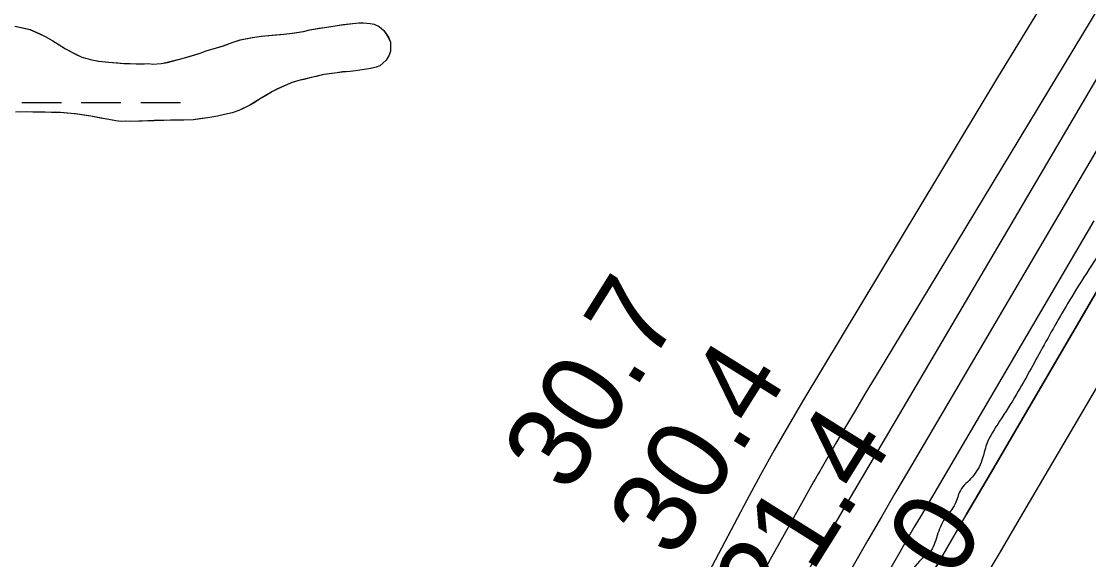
# Model space of a CAD drawing. Extents: x 3297735 to 3335592, y 670436 to 695807.
# Drawn here: x 3318492 to 3319354, y 693409 to 693844 of the extents above; entities that cross this region are included whole.
import ezdxf

# ---------------------------------------------------------------- set-up
doc = ezdxf.new("R2010")
doc.units = 0
for name, color, linetype in [('V-RIVR-EDGE', 7, 'Continuous'), ('V-RIVR-RANG', 7, 'Continuous'), ('V-SITE-VEGE', 7, 'Continuous'), ('V-TOPO-DPTH', 7, 'Continuous'), ('V-TOPO-MAJR', 7, 'Continuous'), ('V-TOPO-MINR', 7, 'Continuous'), ('V-TOPO-WATR', 7, 'Continuous'), ('V-WETL-SWMP', 7, 'Continuous')]:
    doc.layers.add(name, color=color, linetype=linetype)

msp = doc.modelspace()

# ---------------------------------------------------------------- linework, layer by layer
at = {"layer": 'V-RIVR-EDGE'}
msp.add_spline([(3319555.14, 694014.55), (3319548.52, 694002.76), (3319539.36, 693985.79), (3319509.78, 693923.27), (3319496.46, 693903), (3319479.41, 693878.17), (3319464.01, 693854.58), (3319445.27, 693818.98), (3319424.44, 693775.51), (3319406.53, 693740.74), (3319395.69, 693713), (3319386.52, 693693.13), (3319372.79, 693671.61), (3319340.34, 693621.53), (3319316.61, 693580.14), (3319295.79, 693542.89), (3319282.06, 693520.96), (3319271.65, 693502.33), (3319267.89, 693489.49), (3319259.98, 693475.83), (3319250.42, 693465.08), (3319246.25, 693454.32), (3319237.93, 693442.32), (3319231.68, 693428.65), (3319225.43, 693414.99), (3319219.61, 693410.03), (3319205.47, 693391.42), (3319185.09, 693363.28), (3319164.7, 693327.69), (3319143.08, 693301.21), (3319109.39, 693253.21), (3319083.6, 693218.46), (3319061.14, 693187.85), (3319039.52, 693157.64), (3319018.29, 693123.29), (3318994.59, 693091.02), (3318949.68, 693031.86), (3318931.37, 693004.55), (3318913.08, 692981.38), (3318902.25, 692962.76), (3318892.68, 692944.55), (3318876.03, 692916.4), (3318861.86, 692887.84), (3318841.46, 692848.51), (3318822.29, 692807.53), (3318806.46, 692774.41), (3318803.1, 692758.66), (3318804.31, 692744.98), (3318808.02, 692734.61), (3318808.84, 692730.46), (3318817.11, 692725.47), (3318826.63, 692719.23), (3318832.83, 692713), (3318835.72, 692705.53), (3318835.27, 692692.27), (3318829.85, 692681.5), (3318819.88, 692669.09), (3318809.47, 692651.3), (3318783.24, 692602.87), (3318768.67, 692580.52), (3318760.79, 692575.98), (3318753.73, 692573.1), (3318747.11, 692573.94), (3318739.24, 692579.76), (3318735.53, 692585.58), (3318730.56, 692588.49), (3318721.44, 692588.1), (3318700.27, 692573.64), (3318679.48, 692549.66), (3318660.76, 692522.35), (3318646.6, 692493.37), (3318637.03, 692477.64), (3318624.96, 692456.95), (3318607.08, 692434.19), (3318599.98, 692413.49), (3318583.3, 692372.49), (3318565.82, 692342.28), (3318547.09, 692313.73), (3318534.2, 692295.52), (3318512.56, 692258.69), (3318488.02, 692224.76), (3318446.4, 692155.23), (3318418.11, 692112.61), (3318397.31, 692084.47), (3318386.91, 692066.68), (3318376.5, 692048.05), (3318354.44, 692011.22), (3318333.22, 691976.45), (3318316.13, 691940.02), (3318301.57, 691917.67), (3318275.38, 691884.99), (3318265.81, 691873), (3318250.82, 691844.85), (3318236.64, 691808.41), (3318222.07, 691781.09), (3318194.96, 691714.01), (3318179.96, 691684.2), (3318162.07, 691654.82), (3318140.84, 691619.64), (3318130.44, 691603.92), (3318120.89, 691595.24), (3318105.09, 691577.87), (3318090.12, 691558.42), (3318067.68, 691532.37), (3318043.56, 691501.75), (3318020.26, 691465.75), (3317998.21, 691433.06), (3317973.66, 691392.92), (3317962.42, 691371.81), (3317929.95, 691315.1), (3317907.9, 691282.41), (3317889.2, 691263.39), (3317870.48, 691238.16), (3317844.7, 691202.99), (3317833.05, 691186.02), (3317808.09, 691148.78), (3317780.64, 691109.47), (3317756.1, 691076.38), (3317731.98, 691045.35), (3317684.57, 690978.73), (3317668.76, 690954.73), (3317646.3, 690922.04), (3317635.48, 690907.15), (3317629.25, 690900.53), (3317620.1, 690889.36), (3317608.46, 690874.47), (3317601.4, 690867.03), (3317592.67, 690860.42), (3317585.59, 690845.93), (3317576.86, 690836), (3317565.64, 690821.11), (3317549.42, 690801.25), (3317522.4, 690767.75), (3317502.45, 690745), (3317489.97, 690727.62), (3317482.47, 690713.55), (3317479.54, 690701.12), (3317475.78, 690689.94), (3317474.94, 690683.31), (3317467.87, 690674.21), (3317451.65, 690653.94), (3317427.54, 690622.91), (3317406.33, 690593.95), (3317381.8, 690564.58), (3317328.18, 690504.62), (3317308.23, 690483.11), (3317290.78, 690466.16), (3317272.5, 690446.31), (3317248.81, 690422.74), (3317230.94, 690402.48), (3317202.23, 690356.54), (3317170.21, 690314.34), (3317129.47, 690266.36), (3317099.12, 690227.48), (3317085.82, 690212.59), (3317074.19, 690204.33), (3317063.38, 690189.85), (3317045.08, 690163.78), (3317020.95, 690128.61), (3316996.82, 690093.85), (3316970.63, 690059.1), (3316926.98, 690008.23), (3316891.65, 689970.6), (3316861.71, 689930.05), (3316828.03, 689887.86), (3316809.31, 689860.13), (3316797.25, 689841.93), (3316783.53, 689825.38), (3316737.37, 689762.08), (3316714.9, 689728.98), (3316681.64, 689687.61), (3316661.69, 689665.69), (3316647.97, 689646.66), (3316619.68, 689606.11), (3316602.63, 689581.28), (3316583.49, 689551.9), (3316563.93, 689519.62), (3316547.71, 689499.35), (3316541.89, 689491.9), (3316538.57, 689488.6), (3316532.31, 689474.1), (3316523.16, 689461.28), (3316509.03, 689445.15), (3316500.29, 689431.49), (3316493.22, 689419.9), (3316485.73, 689407.9), (3316486.11, 689397.12), (3316486.48, 689375.57), (3316487.29, 689371.01), (3316491.44, 689370.17), (3316493.5, 689366.43), (3316494.29, 689352.75), (3316496.75, 689341.56), (3316502.54, 689336.57), (3316504.2, 689334.08), (3316504.18, 689328.69), (3316501.27, 689325.8), (3316488.83, 689321.27), (3316487.17, 689319.61), (3316487.16, 689316.71), (3316492.96, 689316.7), (3316502.08, 689318.33), (3316508.3, 689318.32), (3316513.27, 689314.99), (3316516.58, 689314.98), (3316524.87, 689314.55), (3316535.62, 689303.33), (3316544.71, 689293.36), (3316545.54, 689290.04), (3316543.46, 689287.97), (3316525.66, 689296.72), (3316509.92, 689304.22), (3316502.06, 689307.14), (3316490.45, 689308.41), (3316482.58, 689308.02), (3316478.02, 689308.03), (3316473.47, 689311.77), (3316449.46, 689323.85), (3316424.59, 689324.74), (3316401.79, 689323.14), (3316381.47, 689318.22), (3316366.54, 689316.18), (3316352.85, 689311.24), (3316334.16, 689295.54), (3316302.2, 689277.79), (3316275.21, 689257.14), (3316266.49, 689249.28), (3316249.02, 689224.04), (3316230.28, 689191.76), (3316217.78, 689162.78), (3316200.69, 689125.93), (3316182.37, 689092.82), (3316162.8, 689054.73), (3316141.17, 689024.94), (3316114.57, 688996.41), (3316081.77, 688971.62), (3316036.89, 688926.14), (3316007.39, 688897.61), (3315987.04, 688880.67), (3315970.01, 688865.79), (3315959.63, 688858.77), (3315957.13, 688852.14), (3315955.46, 688848.42), (3315953.91, 688835.53)], degree=3, dxfattribs=at)
at = {"layer": 'V-SITE-VEGE'}
for p, q in [((3318486.92, 693840.15), (3318493.19, 693838.94)), ((3318493.19, 693838.94), (3318499.13, 693837.4)), ((3318725.11, 693837.13), (3318736.86, 693839.26)), ((3318736.86, 693839.26), (3318742.24, 693839.89)), ((3318742.24, 693839.89), (3318748.96, 693841.06)), ((3318748.96, 693841.06), (3318759.73, 693842.33)), ((3318759.73, 693842.33), (3318764.6, 693842.78)), ((3318764.6, 693842.78), (3318768.31, 693842.86)), ((3318768.31, 693842.86), (3318773.89, 693842.49)), ((3318773.89, 693842.49), (3318777.11, 693841.72)), ((3318777.11, 693841.72), (3318781.03, 693839.96)), ((3318781.03, 693839.96), (3318784.82, 693836.68)), ((3318499.13, 693837.4), (3318506.97, 693834.04)), ((3318506.97, 693834.04), (3318511.4, 693831.95)), ((3318511.4, 693831.95), (3318517.56, 693828.38)), ((3318668.97, 693829.07), (3318678.71, 693831.15)), ((3318678.71, 693831.15), (3318685.93, 693832.16)), ((3318685.93, 693832.16), (3318704.28, 693833.77)), ((3318704.28, 693833.77), (3318711, 693834.61)), ((3318711, 693834.61), (3318719.91, 693836)), ((3318719.91, 693836), (3318725.11, 693837.13)), ((3318784.82, 693836.68), (3318788.49, 693831.2)), ((3318788.49, 693831.2), (3318790.27, 693827.19)), ((3318517.56, 693828.38), (3318527.83, 693821.88)), ((3318527.83, 693821.88), (3318536.02, 693817.52)), ((3318641.36, 693820.16), (3318655.26, 693824.36)), ((3318655.26, 693824.36), (3318663.11, 693827.24)), ((3318663.11, 693827.24), (3318668.97, 693829.07)), ((3318790.27, 693827.19), (3318790.27, 693819.94)), ((3318536.02, 693817.52), (3318540.97, 693815.28)), ((3318540.97, 693815.28), (3318549.12, 693812.94)), ((3318549.12, 693812.94), (3318554.54, 693811.88)), ((3318610.04, 693810.99), (3318623.95, 693814.52)), ((3318623.95, 693814.52), (3318636.51, 693818.36)), ((3318636.51, 693818.36), (3318641.36, 693820.16)), ((3318786.73, 693812.61), (3318781.61, 693808.1)), ((3318789.16, 693816.88), (3318786.73, 693812.61)), ((3318790.27, 693819.94), (3318789.16, 693816.88)), ((3318554.54, 693811.88), (3318562.65, 693811.06)), ((3318562.65, 693811.06), (3318574.98, 693810.17)), ((3318574.98, 693810.17), (3318584.94, 693809.73)), ((3318584.94, 693809.73), (3318591.68, 693809.89)), ((3318591.68, 693809.89), (3318594.88, 693810.13)), ((3318594.88, 693810.13), (3318598.27, 693809.53)), ((3318598.27, 693809.53), (3318605, 693810.03)), ((3318605, 693810.03), (3318610.04, 693810.99)), ((3318757.76, 693803.66), (3318751.54, 693803.18)), ((3318761.97, 693804.1), (3318757.76, 693803.66)), ((3318774.24, 693805.9), (3318761.97, 693804.1)), ((3318778.77, 693807.02), (3318774.24, 693805.9)), ((3318781.61, 693808.1), (3318778.77, 693807.02)), ((3318716.28, 693796.28), (3318710.76, 693794.64)), ((3318736.58, 693801.14), (3318716.28, 693796.28)), ((3318751.54, 693803.18), (3318736.58, 693801.14)), ((3318694.91, 693787.35), (3318685.76, 693781.91)), ((3318698.58, 693789.29), (3318694.91, 693787.35)), ((3318707.08, 693793.2), (3318698.58, 693789.29)), ((3318710.76, 693794.64), (3318707.08, 693793.2)), ((3318680.11, 693778.4), (3318676.61, 693776.46)), ((3318685.76, 693781.91), (3318680.11, 693778.4)), ((3318496.31, 693770.89), (3318487.38, 693770.68)), ((3318501.54, 693770.67), (3318496.31, 693770.89)), ((3318505.42, 693770.76), (3318501.54, 693770.67)), ((3318511.32, 693770.73), (3318505.42, 693770.76)), ((3318516.55, 693770.52), (3318511.32, 693770.73)), ((3318519.59, 693770.59), (3318516.55, 693770.52)), ((3318523.64, 693770.35), (3318519.59, 693770.59)), ((3318532.42, 693769.71), (3318523.64, 693770.35)), ((3318539.52, 693768.86), (3318532.42, 693769.71)), ((3318662.43, 693770.23), (3318656.22, 693768.74)), ((3318667.78, 693772.04), (3318662.43, 693770.23)), ((3318676.61, 693776.46), (3318667.78, 693772.04)), ((3318548.33, 693767.38), (3318539.52, 693768.86)), ((3318568.48, 693763.64), (3318548.33, 693767.38)), ((3318572.71, 693763.23), (3318568.48, 693763.64)), ((3318576.59, 693763.33), (3318572.71, 693763.23)), ((3318580.3, 693763.24), (3318576.59, 693763.33)), ((3318599.34, 693763.86), (3318580.3, 693763.24)), ((3318607.27, 693763.88), (3318599.34, 693763.86)), ((3318612.65, 693764.17), (3318607.27, 693763.88)), ((3318623.44, 693764.26), (3318612.65, 693764.17)), ((3318631.19, 693764.61), (3318623.44, 693764.26)), ((3318642.46, 693766.05), (3318631.19, 693764.61)), ((3318645.98, 693766.81), (3318642.46, 693766.05)), ((3318650.52, 693767.59), (3318645.98, 693766.81)), ((3318656.22, 693768.74), (3318650.52, 693767.59))]:
    msp.add_line(p, q, dxfattribs=at)
at = {"layer": 'V-TOPO-DPTH'}
for points in [[(3319397.53, 693802.93), (3319208.57, 693481.24), (3319197.61, 693462.51), (3319186.68, 693443.76), (3319175.8, 693424.98), (3319164.96, 693406.17), (3318890.81, 692929.09), (3318889.57, 692926.93), (3318887.11, 692922.6), (3318885.89, 692920.44), (3318883.86, 692916.84), (3318883.24, 692915.73), (3318881.62, 692912.8), (3318879.81, 692909.49), (3318878.9, 692907.83), (3318878, 692906.18), (3318861.29, 692875.47), (3318852.04, 692858.46), (3318842.79, 692841.44), (3318833.53, 692824.43), (3318824.28, 692807.42), (3318495.08, 692202.06)], [(3318762.29, 692573.01), (3318806.07, 692650.9), (3318849.52, 692728.97), (3318916.57, 692850.34), (3318926.28, 692867.85), (3318936.02, 692885.34), (3318945.82, 692902.8), (3318955.65, 692920.23), (3319122.05, 693214.3), (3319140.91, 693247.5), (3319159.83, 693280.66), (3319178.85, 693313.76), (3319197.95, 693346.82), (3319217.11, 693379.84), (3319236.3, 693412.85), (3319255.52, 693445.83), (3319274.77, 693478.8), (3319305.8, 693531.86), (3319340.53, 693591.37), (3319375.22, 693650.92)], [(3318762.29, 692573.01), (3318806.07, 692650.9), (3318849.52, 692728.97), (3318916.57, 692850.34), (3318926.28, 692867.85), (3318936.02, 692885.34), (3318945.82, 692902.8), (3318955.65, 692920.23), (3319122.05, 693214.3), (3319140.91, 693247.5), (3319159.83, 693280.66), (3319178.85, 693313.76), (3319197.95, 693346.82), (3319217.11, 693379.84), (3319236.3, 693412.85), (3319255.52, 693445.83), (3319274.77, 693478.8), (3319305.8, 693531.86), (3319340.53, 693591.37), (3319375.22, 693650.92)]]:
    msp.add_lwpolyline(points, dxfattribs=at)
at = {"layer": 'V-TOPO-MAJR'}
msp.add_lwpolyline([(3319313.56, 693852.85), (3319280.55, 693798.62), (3319123.25, 693537.44), (3319111.55, 693517.64), (3319100.09, 693497.72), (3319088.97, 693477.61), (3319078.07, 693457.37), (3318938.07, 693191.84), (3318917.38, 693152.67), (3318896.66, 693113.51), (3318875.91, 693074.37), (3318855.12, 693035.25), (3318822, 692973.01), (3318817.73, 692965.03), (3318813.44, 692957.06), (3318809.11, 692949.11), (3318804.75, 692941.17), (3318509.85, 692406.6)], dxfattribs=at)
at = {"layer": 'V-TOPO-MINR'}
for points in [[(3319458.23, 694014.45), (3319181.56, 693556.63), (3319173.57, 693543.32), (3319165.62, 693529.99), (3319157.74, 693516.62), (3319149.9, 693503.22), (3319136.82, 693480.7), (3319135.57, 693478.53), (3319133.09, 693474.19), (3319131.87, 693472.01), (3319119.33, 693449.58), (3319111.85, 693436.18), (3319104.37, 693422.78), (3319096.9, 693409.37), (3319089.43, 693395.96), (3318863.75, 692990.42), (3318850.58, 692966.73), (3318837.43, 692943.03), (3318824.29, 692919.32), (3318811.17, 692895.6), (3318709.69, 692711.94), (3318656.45, 692615.16), (3318603.44, 692518.24)], [(3319364.99, 693805.47), (3319198.47, 693522.45), (3319179.99, 693490.94), (3319161.57, 693459.39), (3319143.25, 693427.79), (3319124.99, 693396.16), (3319090.7, 693336.53), (3319055.43, 693275), (3319020.29, 693213.4), (3318985.34, 693151.69), (3318950.51, 693089.91), (3318873.91, 692953.53), (3318867.2, 692941.53), (3318860.49, 692929.53), (3318853.82, 692917.51), (3318847.17, 692905.48), (3318801.31, 692822.39), (3318771.81, 692768.77), (3318742.39, 692715.1), (3318713.11, 692661.36), (3318683.92, 692607.57)], [(3319397.53, 693802.93), (3319208.57, 693481.24), (3319197.61, 693462.51), (3319186.68, 693443.76), (3319175.8, 693424.98), (3319164.96, 693406.17), (3318890.81, 692929.09), (3318889.57, 692926.93), (3318887.11, 692922.6), (3318885.89, 692920.44), (3318883.86, 692916.84), (3318883.24, 692915.73), (3318881.62, 692912.8), (3318879.81, 692909.49), (3318878.9, 692907.83), (3318878, 692906.18), (3318861.29, 692875.47), (3318852.04, 692858.46), (3318842.79, 692841.44), (3318833.53, 692824.43), (3318824.28, 692807.42), (3318495.08, 692202.06)], [(3319504.71, 693794.02), (3319296.15, 693438.76), (3319282.54, 693415.63), (3319268.9, 693392.52), (3319255.22, 693369.44), (3319241.51, 693346.38), (3319052.26, 693028.68), (3319036.75, 693002.52), (3319021.33, 692976.33), (3319006.01, 692950.06), (3318990.77, 692923.75), (3318966.24, 692881.19), (3318963.34, 692876.12), (3318960.45, 692871.05), (3318957.59, 692865.95), (3318954.75, 692860.85), (3318934.95, 692825.09), (3318922.15, 692802.14), (3318909.26, 692779.24), (3318896.22, 692756.42), (3318883.08, 692733.66), (3318534.83, 692134.49)], [(3319358.13, 693682.81), (3319333.43, 693640.56), (3319308.71, 693598.31), (3319283.96, 693556.09), (3319259.18, 693513.88), (3319217.85, 693443.52), (3319213.74, 693436.49), (3319209.64, 693429.45), (3319205.56, 693422.4), (3319201.49, 693415.34), (3319152.07, 693329.2), (3319123.39, 693279.02), (3319094.82, 693228.78), (3319066.4, 693178.45), (3319038.1, 693128.05), (3318944.49, 692960.75), (3318927.59, 692930.46), (3318910.73, 692900.14), (3318893.95, 692869.78), (3318877.22, 692839.4), (3318695.95, 692509.33)]]:
    msp.add_lwpolyline(points, dxfattribs=at)
at = {"layer": 'V-TOPO-WATR'}
msp.add_lwpolyline([(3319375.22, 693650.92), (3319340.53, 693591.37), (3319305.8, 693531.86), (3319274.77, 693478.8), (3319255.52, 693445.83), (3319236.3, 693412.85), (3319217.11, 693379.84), (3319197.95, 693346.82), (3319178.85, 693313.76), (3319159.83, 693280.66), (3319140.91, 693247.5), (3319122.05, 693214.3), (3318955.65, 692920.23), (3318945.82, 692902.8), (3318936.02, 692885.34), (3318926.28, 692867.85), (3318916.57, 692850.34), (3318849.52, 692728.97), (3318806.07, 692650.9), (3318762.29, 692573.01)], dxfattribs=at)
at = {"layer": 'V-WETL-SWMP'}
for p, q in [((3318486.83, 693840.15), (3318493.1, 693838.95)), ((3318493.1, 693838.95), (3318499.04, 693837.4)), ((3318725.01, 693837.14), (3318732.4, 693838.49)), ((3318732.4, 693838.49), (3318736.77, 693839.27)), ((3318736.77, 693839.27), (3318742.15, 693839.9)), ((3318742.15, 693839.9), (3318745.51, 693840.48)), ((3318745.51, 693840.48), (3318748.87, 693841.07)), ((3318748.87, 693841.07), (3318752.06, 693841.48)), ((3318752.06, 693841.48), (3318759.63, 693842.33)), ((3318759.63, 693842.33), (3318764.51, 693842.78)), ((3318764.51, 693842.78), (3318768.22, 693842.87)), ((3318768.22, 693842.87), (3318773.79, 693842.5)), ((3318773.79, 693842.5), (3318777.01, 693841.73)), ((3318777.01, 693841.73), (3318780.93, 693839.97)), ((3318780.93, 693839.97), (3318784.72, 693836.68)), ((3318499.04, 693837.4), (3318506.87, 693834.04)), ((3318506.87, 693834.04), (3318511.31, 693831.96)), ((3318511.31, 693831.96), (3318517.46, 693828.39)), ((3318668.88, 693829.07), (3318678.61, 693831.16)), ((3318678.61, 693831.16), (3318685.84, 693832.17)), ((3318685.84, 693832.17), (3318697.11, 693833.11)), ((3318697.11, 693833.11), (3318704.18, 693833.78)), ((3318704.18, 693833.78), (3318710.91, 693834.61)), ((3318710.91, 693834.61), (3318719.81, 693836)), ((3318719.81, 693836), (3318725.01, 693837.14)), ((3318784.72, 693836.68), (3318788.39, 693831.2)), ((3318788.39, 693831.2), (3318790.17, 693827.2)), ((3318517.46, 693828.39), (3318521.06, 693826.11)), ((3318521.06, 693826.11), (3318527.73, 693821.88)), ((3318527.73, 693821.88), (3318535.93, 693817.52)), ((3318641.26, 693820.16), (3318649.63, 693822.72)), ((3318649.63, 693822.72), (3318655.16, 693824.37)), ((3318655.16, 693824.37), (3318663.02, 693827.25)), ((3318663.02, 693827.25), (3318668.88, 693829.07)), ((3318790.17, 693827.2), (3318790.17, 693819.95)), ((3318535.93, 693817.52), (3318540.87, 693815.28)), ((3318540.87, 693815.28), (3318549.02, 693812.94)), ((3318549.02, 693812.94), (3318554.44, 693811.89)), ((3318609.94, 693811), (3318618.49, 693813.22)), ((3318618.49, 693813.22), (3318623.86, 693814.53)), ((3318623.86, 693814.53), (3318628.71, 693815.99)), ((3318628.71, 693815.99), (3318636.41, 693818.36)), ((3318636.41, 693818.36), (3318641.26, 693820.16)), ((3318786.63, 693812.61), (3318781.51, 693808.11)), ((3318789.06, 693816.88), (3318786.63, 693812.61)), ((3318790.17, 693819.95), (3318789.06, 693816.88)), ((3318554.44, 693811.89), (3318562.56, 693811.07)), ((3318562.56, 693811.07), (3318569.99, 693810.57)), ((3318569.99, 693810.57), (3318574.89, 693810.17)), ((3318574.89, 693810.17), (3318579.95, 693809.96)), ((3318579.95, 693809.96), (3318584.85, 693809.73)), ((3318584.85, 693809.73), (3318591.59, 693809.89)), ((3318591.59, 693809.89), (3318594.79, 693810.14)), ((3318594.79, 693810.14), (3318598.17, 693809.54)), ((3318598.17, 693809.54), (3318604.91, 693810.04)), ((3318604.91, 693810.04), (3318609.94, 693811)), ((3318757.67, 693803.67), (3318751.44, 693803.19)), ((3318761.87, 693804.11), (3318757.67, 693803.67)), ((3318767.42, 693804.91), (3318761.87, 693804.11)), ((3318774.14, 693805.91), (3318767.42, 693804.91)), ((3318778.67, 693807.03), (3318774.14, 693805.91)), ((3318781.51, 693808.11), (3318778.67, 693807.03)), ((3318716.19, 693796.29), (3318710.66, 693794.64)), ((3318720.21, 693797.23), (3318716.19, 693796.29)), ((3318726.25, 693798.72), (3318720.21, 693797.23)), ((3318730.11, 693799.65), (3318726.25, 693798.72)), ((3318736.48, 693801.15), (3318730.11, 693799.65)), ((3318740.68, 693801.75), (3318736.48, 693801.15)), ((3318747.07, 693802.58), (3318740.68, 693801.75)), ((3318751.44, 693803.19), (3318747.07, 693802.58)), ((3318694.81, 693787.36), (3318689.33, 693784.02)), ((3318698.48, 693789.3), (3318694.81, 693787.36)), ((3318703.81, 693791.78), (3318698.48, 693789.3)), ((3318706.99, 693793.21), (3318703.81, 693791.78)), ((3318710.66, 693794.64), (3318706.99, 693793.21)), ((3318492.52, 693778.45), (3318524.52, 693778.45)), ((3318540.52, 693778.45), (3318572.52, 693778.45)), ((3318588.52, 693778.45), (3318620.52, 693778.45)), ((3318680.01, 693778.41), (3318676.52, 693776.47)), ((3318685.67, 693781.91), (3318680.01, 693778.41)), ((3318689.33, 693784.02), (3318685.67, 693781.91)), ((3318496.21, 693770.89), (3318490.48, 693770.76)), ((3318501.45, 693770.68), (3318496.21, 693770.89)), ((3318505.32, 693770.77), (3318501.45, 693770.68)), ((3318511.22, 693770.74), (3318505.32, 693770.77)), ((3318516.46, 693770.52), (3318511.22, 693770.74)), ((3318519.49, 693770.6), (3318516.46, 693770.52)), ((3318523.54, 693770.35), (3318519.49, 693770.6)), ((3318528.78, 693769.97), (3318523.54, 693770.35)), ((3318532.33, 693769.72), (3318528.78, 693769.97)), ((3318535.71, 693769.29), (3318532.33, 693769.72)), ((3318539.43, 693768.87), (3318535.71, 693769.29)), ((3318662.33, 693770.24), (3318656.13, 693768.74)), ((3318667.69, 693772.05), (3318662.33, 693770.24)), ((3318671.35, 693773.82), (3318667.69, 693772.05)), ((3318676.52, 693776.47), (3318671.35, 693773.82)), ((3318542.65, 693768.27), (3318539.43, 693768.87)), ((3318548.23, 693767.39), (3318542.65, 693768.27)), ((3318552.13, 693766.64), (3318548.23, 693767.39)), ((3318557.72, 693765.59), (3318552.13, 693766.64)), ((3318561.27, 693765), (3318557.72, 693765.59)), ((3318568.39, 693763.65), (3318561.27, 693765)), ((3318572.61, 693763.24), (3318568.39, 693763.65)), ((3318576.49, 693763.33), (3318572.61, 693763.24)), ((3318580.2, 693763.25), (3318576.49, 693763.33)), ((3318586.94, 693763.41), (3318580.2, 693763.25)), ((3318594.19, 693763.75), (3318586.94, 693763.41)), ((3318599.24, 693763.87), (3318594.19, 693763.75)), ((3318607.17, 693763.88), (3318599.24, 693763.87)), ((3318612.56, 693764.18), (3318607.17, 693763.88)), ((3318623.35, 693764.26), (3318612.56, 693764.18)), ((3318631.1, 693764.61), (3318623.35, 693764.26)), ((3318635.97, 693765.23), (3318631.1, 693764.61)), ((3318642.36, 693766.06), (3318635.97, 693765.23)), ((3318645.89, 693766.82), (3318642.36, 693766.06)), ((3318650.42, 693767.6), (3318645.89, 693766.82)), ((3318656.13, 693768.74), (3318650.42, 693767.6))]:
    msp.add_line(p, q, dxfattribs=at)

# ---------------------------------------------------------------- texts
at = {"layer": 'V-RIVR-RANG'}
for s, rotation, p in [('30.7', 57.93833, (3318934.17, 693461.1)), ('30.4', 57.93833, (3319019.05, 693408.23)), ('21.4', 57.93833, (3319103.93, 693355.35)), ('4.0', 58.22036, (3319205.37, 693328.1))]:
    msp.add_text(s, height=67, rotation=rotation, dxfattribs=at).set_placement(p)

doc.saveas('drawing.dxf')
